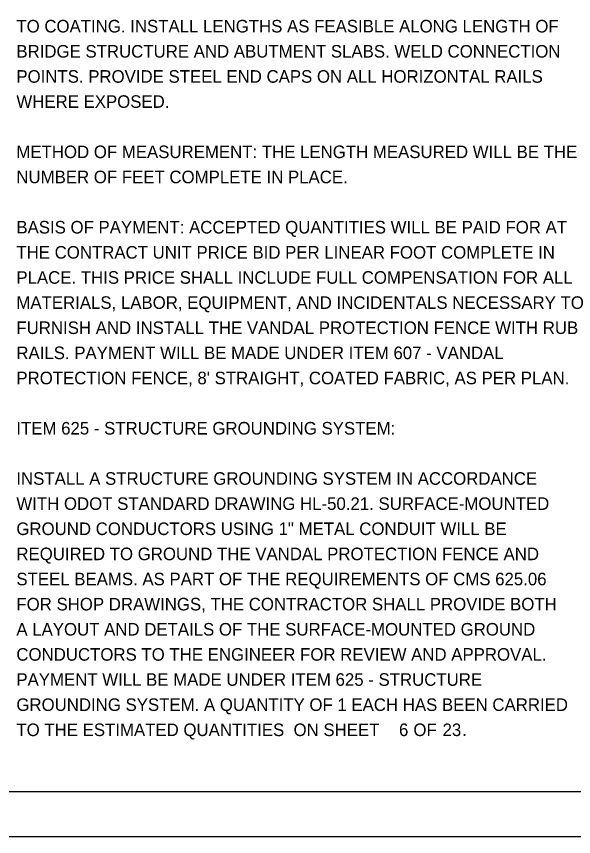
# Model space of a CAD drawing. Extents: x 0 to 34, y 0 to 22.
# Drawn here: x 24.66 to 30.87, y 0 to 9.14 of the extents above; entities that cross this region are included whole.
import ezdxf

# ---------------------------------------------------------------- set-up
doc = ezdxf.new("R2010")
doc.units = 0
for name, color, linetype in [('BR_P_Gen_Text', 7, 'Continuous'), ('SH_Border', 7, 'Continuous'), ('SH_Cut_Line', 7, 'Continuous')]:
    doc.layers.add(name, color=color, linetype=linetype)

msp = doc.modelspace()

# ---------------------------------------------------------------- linework, layer by layer
at = {"layer": 'SH_Border'}
msp.add_lwpolyline([(1.5, 21.5), (33.5, 21.5), (33.5, 0.5), (1.5, 0.5)], close=True, dxfattribs=at)
at = {"layer": 'SH_Cut_Line'}
msp.add_lwpolyline([(0, 0), (34, 0), (34, 22), (0, 22)], close=True, dxfattribs=at)

# ---------------------------------------------------------------- texts
at = {"layer": 'BR_P_Gen_Text'}
for s, p in [('TO COATING. INSTALL LENGTHS AS FEASIBLE ALONG LENGTH OF ', (24.66, 8.96)), ('BRIDGE STRUCTURE AND ABUTMENT SLABS. WELD CONNECTION ', (24.66, 8.68)), ('POINTS. PROVIDE STEEL END CAPS ON ALL HORIZONTAL RAILS ', (24.66, 8.4)), ('WHERE EXPOSED.', (24.66, 8.12)), ('METHOD OF MEASUREMENT: THE LENGTH MEASURED WILL BE THE ', (24.66, 7.56)), ('NUMBER OF FEET COMPLETE IN PLACE.', (24.66, 7.28)), ('BASIS OF PAYMENT: ACCEPTED QUANTITIES WILL BE PAID FOR AT ', (24.66, 6.72)), ('THE CONTRACT UNIT PRICE BID PER LINEAR FOOT COMPLETE IN ', (24.66, 6.44)), ('PLACE. THIS PRICE SHALL INCLUDE FULL COMPENSATION FOR ALL ', (24.66, 6.16)), ('MATERIALS, LABOR, EQUIPMENT, AND INCIDENTALS NECESSARY TO ', (24.66, 5.88)), ('FURNISH AND INSTALL THE VANDAL PROTECTION FENCE WITH RUB ', (24.66, 5.6)), ('RAILS. PAYMENT WILL BE MADE UNDER ITEM 607 - VANDAL ', (24.66, 5.32)), ("PROTECTION FENCE, 8' STRAIGHT, COATED FABRIC, AS PER PLAN.", (24.66, 5.04)), ('ITEM 625 - STRUCTURE GROUNDING SYSTEM:', (24.66, 4.48)), ('INSTALL A STRUCTURE GROUNDING SYSTEM IN ACCORDANCE ', (24.66, 3.92)), ('WITH ODOT STANDARD DRAWING HL-50.21. SURFACE-MOUNTED ', (24.66, 3.64)), ('GROUND CONDUCTORS USING 1" METAL CONDUIT WILL BE ', (24.66, 3.36)), ('REQUIRED TO GROUND THE VANDAL PROTECTION FENCE AND ', (24.66, 3.08)), ('STEEL BEAMS. AS PART OF THE REQUIREMENTS OF CMS 625.06 ', (24.66, 2.8)), ('FOR SHOP DRAWINGS, THE CONTRACTOR SHALL PROVIDE BOTH ', (24.66, 2.52)), ('A LAYOUT AND DETAILS OF THE SURFACE-MOUNTED GROUND ', (24.66, 2.24)), ('CONDUCTORS TO THE ENGINEER FOR REVIEW AND APPROVAL. ', (24.66, 1.96)), ('PAYMENT WILL BE MADE UNDER ITEM 625 - STRUCTURE ', (24.66, 1.68)), ('GROUNDING SYSTEM. A QUANTITY OF 1 EACH HAS BEEN CARRIED ', (24.66, 1.4)), ('TO THE ESTIMATED QUANTITIES  ON SHEET ', (24.66, 1.12)), ('6', (28.9243, 1.12)), (' OF ', (29.0331, 1.12)), ('23', (29.4099, 1.12)), ('.', (29.6273, 1.12))]:
    msp.add_text(s, height=0.14, dxfattribs=at).set_placement(p)

doc.saveas('drawing.dxf')
